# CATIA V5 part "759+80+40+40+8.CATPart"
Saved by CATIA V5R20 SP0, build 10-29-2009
Part number: 759+80+40+40+8
Revision: TUTTO
Definition: NON CONOSCIUTO
Nomenclature: 759+80+40+40+8
Source: Unknown
Bounding box of the stored display mesh (mm): x -40 to 40, y -20 to 20, z 0 to 40
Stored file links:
  C:\Users\Utente\Desktop\IO LAVORO\3D X SITO CF\X 3D SITO CF 27-09-2020\759\759+80+40+40+8.CATPart
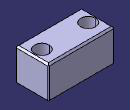
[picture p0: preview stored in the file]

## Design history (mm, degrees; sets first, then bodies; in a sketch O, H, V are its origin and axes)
Body1 "Smusso4" (main body)
  Solid1: solid without history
